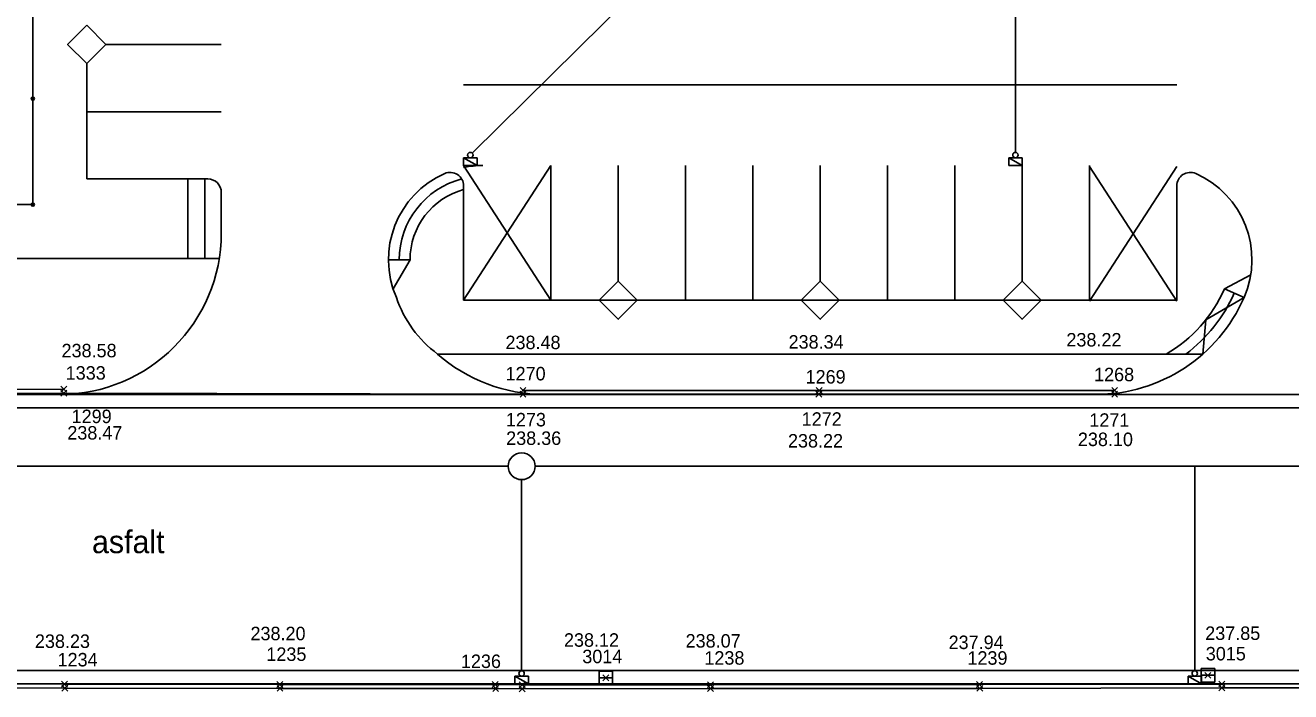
# Model space of a CAD drawing. Extents: x -264205 to -263615, y -1242401 to -1242031.
# Drawn here: x -263972.35 to -263925.35, y -1242312.52 to -1242287.78 of the extents above; entities that cross this region are included whole.
import ezdxf

# ---------------------------------------------------------------- set-up
doc = ezdxf.new("R2010")
doc.units = 0
for name, color, linetype in [('BODY_SYMBOL A CISLO_2-1', 7, 'Continuous'), ('BODY_VYSKA_2-1', 7, 'Continuous'), ('KOORDINACNA_SITUACIA_DSP', 7, 'Continuous'), ('POPIS', 7, 'Continuous'), ('PROJEKT_DRS_TDZ_VODOROVNE', 7, 'Continuous'), ('ROZHRANIE_SO_20-1_a_20-2', 7, 'Continuous'), ('SO_20-1_OBRUBNIKY_DOLNA_HRANA', 7, 'Continuous'), ('SO_20-1_OBRUBNIKY_HORNA_HRANA', 7, 'Continuous'), ('SO_20-1_UV', 7, 'Continuous')]:
    doc.layers.add(name, color=color, linetype=linetype)

msp = doc.modelspace()

# ---------------------------------------------------------------- linework, layer by layer
at = {"layer": 'BODY_SYMBOL A CISLO_2-1'}
for p, q in [((-263971.024, -1242301.4), (-263970.802, -1242301.18)), ((-263970.802, -1242301.4), (-263971.024, -1242301.18)), ((-263971.023, -1242301.549), (-263970.802, -1242301.328)), ((-263970.802, -1242301.549), (-263971.023, -1242301.328)), ((-263953.973, -1242301.441), (-263953.752, -1242301.22)), ((-263953.752, -1242301.441), (-263953.973, -1242301.22)), ((-263953.973, -1242301.588), (-263953.752, -1242301.367)), ((-263953.752, -1242301.588), (-263953.973, -1242301.367)), ((-263942.987, -1242301.586), (-263942.766, -1242301.366)), ((-263942.766, -1242301.586), (-263942.987, -1242301.366)), ((-263942.971, -1242301.448), (-263942.75, -1242301.227)), ((-263942.75, -1242301.448), (-263942.971, -1242301.227)), ((-263931.998, -1242301.441), (-263931.777, -1242301.22)), ((-263931.777, -1242301.441), (-263931.998, -1242301.22)), ((-263931.998, -1242301.585), (-263931.777, -1242301.363)), ((-263931.777, -1242301.585), (-263931.998, -1242301.363)), ((-263971.003, -1242312.353), (-263970.781, -1242312.133)), ((-263970.781, -1242312.353), (-263971.003, -1242312.133)), ((-263963.002, -1242312.359), (-263962.78, -1242312.137)), ((-263962.78, -1242312.359), (-263963.002, -1242312.137)), ((-263955.003, -1242312.366), (-263954.782, -1242312.144)), ((-263954.782, -1242312.366), (-263955.003, -1242312.144)), ((-263954.003, -1242312.377), (-263953.781, -1242312.156)), ((-263953.781, -1242312.377), (-263954.003, -1242312.156)), ((-263950.897, -1242312.115), (-263950.676, -1242311.894)), ((-263950.676, -1242312.115), (-263950.897, -1242311.894)), ((-263947.011, -1242312.372), (-263946.79, -1242312.15)), ((-263946.79, -1242312.372), (-263947.011, -1242312.15)), ((-263937.014, -1242312.363), (-263936.793, -1242312.143)), ((-263936.793, -1242312.363), (-263937.014, -1242312.143)), ((-263928.533, -1242312.022), (-263928.312, -1242311.802)), ((-263928.312, -1242312.022), (-263928.533, -1242311.802)), ((-263928.019, -1242312.346), (-263927.799, -1242312.124)), ((-263927.799, -1242312.346), (-263928.019, -1242312.124)), ((-263928.019, -1242312.346), (-263927.799, -1242312.126)), ((-263927.799, -1242312.346), (-263928.019, -1242312.126)), ((-263970.993, -1242312.498), (-263970.772, -1242312.276)), ((-263970.772, -1242312.498), (-263970.993, -1242312.276)), ((-263962.998, -1242312.507), (-263962.777, -1242312.285)), ((-263962.777, -1242312.507), (-263962.998, -1242312.285)), ((-263954.989, -1242312.514), (-263954.768, -1242312.292)), ((-263954.768, -1242312.514), (-263954.989, -1242312.292)), ((-263954.007, -1242312.521), (-263953.785, -1242312.299)), ((-263953.785, -1242312.521), (-263954.007, -1242312.299)), ((-263947.006, -1242312.516), (-263946.785, -1242312.296)), ((-263946.785, -1242312.516), (-263947.006, -1242312.296)), ((-263937.009, -1242312.507), (-263936.788, -1242312.285)), ((-263936.788, -1242312.507), (-263937.009, -1242312.285)), ((-263928.018, -1242312.492), (-263927.796, -1242312.271)), ((-263927.796, -1242312.492), (-263928.018, -1242312.271)), ((-263928.017, -1242312.492), (-263927.796, -1242312.272)), ((-263927.796, -1242312.492), (-263928.017, -1242312.272))]:
    msp.add_line(p, q, dxfattribs=at)
at = {"layer": 'KOORDINACNA_SITUACIA_DSP'}
for p, q in [((-263972.068, -1242294.432), (-263972.068, -1242255.057)), ((-263955.747, -1242292.522), (-263947.464, -1242284.334)), ((-263935.574, -1242292.492), (-263935.574, -1242284.343)), ((-263970.068, -1242293.482), (-263970.068, -1242289.189)), ((-263972.128, -1242290.495), (-263972.008, -1242290.495)), ((-263972.068, -1242290.555), (-263972.068, -1242290.435)), ((-263956.068, -1242292.692), (-263955.568, -1242292.692)), ((-263956.068, -1242292.982), (-263956.068, -1242292.692)), ((-263956.068, -1242292.692), (-263955.568, -1242292.982)), ((-263956.068, -1242292.692), (-263955.568, -1242292.982)), ((-263955.568, -1242292.692), (-263956.068, -1242292.692)), ((-263955.568, -1242292.692), (-263955.568, -1242292.982)), ((-263955.568, -1242292.982), (-263955.568, -1242292.692)), ((-263935.824, -1242292.692), (-263935.324, -1242292.692)), ((-263935.824, -1242292.982), (-263935.824, -1242292.692)), ((-263935.824, -1242292.692), (-263935.324, -1242292.982)), ((-263935.824, -1242292.692), (-263935.324, -1242292.982)), ((-263935.324, -1242292.692), (-263935.824, -1242292.692)), ((-263935.324, -1242292.692), (-263935.324, -1242292.982)), ((-263935.324, -1242292.982), (-263935.324, -1242292.692)), ((-263955.568, -1242292.982), (-263956.068, -1242292.982)), ((-263935.324, -1242292.982), (-263935.824, -1242292.982)), ((-263970.068, -1242293.482), (-263965.568, -1242293.482)), ((-263966.314, -1242293.482), (-263966.314, -1242296.432)), ((-263965.684, -1242293.482), (-263965.684, -1242296.432)), ((-263956.068, -1242297.982), (-263956.068, -1242293.737)), ((-263929.58, -1242297.982), (-263929.58, -1242293.737)), ((-263972.068, -1242294.492), (-263972.068, -1242294.372)), ((-263965.068, -1242293.982), (-263965.068, -1242295.482)), ((-264045.118, -1242294.432), (-263972.068, -1242294.432)), ((-263972.128, -1242294.432), (-263972.008, -1242294.432)), ((-263927.814, -1242297.562), (-263926.833, -1242297.035)), ((-263927.814, -1242297.562), (-263927.081, -1242297.882)), ((-263929.58, -1242297.982), (-263956.068, -1242297.982)), ((-263928.612, -1242299.982), (-263957.036, -1242299.982)), ((-263971.068, -1242301.482), (-264112.961, -1242301.482)), ((-263932.58, -1242301.482), (-263953.068, -1242301.482)), ((-263954.413, -1242304.147), (-264003.396, -1242304.147)), ((-263904.413, -1242304.147), (-263953.413, -1242304.147)), ((-263928.913, -1242311.742), (-263928.913, -1242304.147)), ((-263953.913, -1242311.742), (-263953.913, -1242304.647)), ((-263954.163, -1242311.942), (-263953.663, -1242311.942)), ((-263954.163, -1242312.232), (-263954.163, -1242311.942)), ((-263954.163, -1242311.942), (-263953.663, -1242312.232)), ((-263954.163, -1242311.942), (-263953.663, -1242312.232)), ((-263953.663, -1242311.942), (-263954.163, -1242311.942)), ((-263953.663, -1242311.942), (-263953.663, -1242312.232)), ((-263953.663, -1242312.232), (-263953.663, -1242311.942)), ((-263929.163, -1242311.942), (-263928.663, -1242311.942)), ((-263929.163, -1242312.232), (-263929.163, -1242311.942)), ((-263929.163, -1242311.942), (-263928.663, -1242312.232)), ((-263929.163, -1242311.942), (-263928.663, -1242312.232)), ((-263928.663, -1242311.942), (-263929.163, -1242311.942)), ((-263928.663, -1242311.942), (-263928.663, -1242312.232)), ((-263928.663, -1242312.232), (-263928.663, -1242311.942)), ((-263980.94, -1242312.232), (-263857.327, -1242312.232)), ((-263953.663, -1242312.232), (-263954.163, -1242312.232)), ((-263928.663, -1242312.232), (-263929.163, -1242312.232))]:
    msp.add_line(p, q, dxfattribs=at)
for points in [[(-263970.068, -1242287.775), (-263969.361, -1242288.482), (-263970.068, -1242289.189), (-263970.775, -1242288.482)], [(-263949.617, -1242297.982), (-263950.324, -1242297.275), (-263951.031, -1242297.982), (-263950.324, -1242298.689)], [(-263942.117, -1242297.982), (-263942.824, -1242297.275), (-263943.531, -1242297.982), (-263942.824, -1242298.689)], [(-263934.617, -1242297.982), (-263935.324, -1242297.275), (-263936.031, -1242297.982), (-263935.324, -1242298.689)]]:
    msp.add_lwpolyline(points, close=True, dxfattribs=at)
for points in [[(-263965.143, -1242296.432), (-264120.018, -1242296.432), (-264120.282, -1242296.432)], [(-263958.859, -1242296.482), (-263958.059, -1242296.482), (-263958.688, -1242297.562)], [(-263927.081, -1242297.882), (-263928.506, -1242298.713), (-263928.612, -1242299.982)]]:
    msp.add_lwpolyline(points, dxfattribs=at)
for centre, radius in [((-263972.068, -1242290.495), 0.06), ((-263955.818, -1242292.592), 0.1), ((-263935.574, -1242292.592), 0.1), ((-263972.068, -1242294.432), 0.06), ((-263953.913, -1242304.147), 0.5), ((-263953.913, -1242311.842), 0.1), ((-263928.913, -1242311.842), 0.1)]:
    msp.add_circle(centre, radius, dxfattribs=at)
for centre, radius, start, end in [((-263955.359, -1242296.482), 3.5, 113.7599, 203.5782), ((-263956.568, -1242293.737), 0.5, 0, 113.7599), ((-263929.08, -1242293.737), 0.5, 66.2401, 180), ((-263930.289, -1242296.482), 3.5, 336.4218, 66.2401), ((-263965.568, -1242293.982), 0.5, 0, 90), ((-263955.359, -1242296.482), 3.1, 104.5457, 180), ((-263955.359, -1242296.482), 2.7, 105.2176, 180), ((-263971.068, -1242295.482), 6, 270, 0), ((-263932.58, -1242295.482), 5.2, 300.0733, 336.4218), ((-263954.444, -1242296.485), 4.353, 198.7173, 233.4513), ((-263932.58, -1242295.482), 6, 270, 336.4218), ((-263932.58, -1242295.482), 5.6, 306.5275, 336.4218), ((-263953.068, -1242295.482), 6, 228.5904, 270)]:
    msp.add_arc(centre, radius, start, end, dxfattribs=at)
at = {"layer": 'PROJEKT_DRS_TDZ_VODOROVNE'}
for p, q in [((-263965.068, -1242288.482), (-263969.361, -1242288.482)), ((-263929.58, -1242289.982), (-263956.068, -1242289.982)), ((-263965.068, -1242290.982), (-263970.068, -1242290.982)), ((-263956.069, -1242297.982), (-263952.825, -1242292.982)), ((-263956.069, -1242292.982), (-263952.825, -1242297.982)), ((-263952.824, -1242297.982), (-263952.824, -1242292.982)), ((-263950.324, -1242297.275), (-263950.324, -1242292.982)), ((-263947.824, -1242297.982), (-263947.824, -1242292.982)), ((-263945.324, -1242297.982), (-263945.324, -1242292.982)), ((-263942.824, -1242297.275), (-263942.824, -1242292.982)), ((-263940.324, -1242297.982), (-263940.324, -1242292.982)), ((-263937.824, -1242297.982), (-263937.824, -1242292.982)), ((-263935.324, -1242297.275), (-263935.324, -1242292.982)), ((-263932.824, -1242297.982), (-263932.824, -1242292.982)), ((-263932.824, -1242298.014), (-263929.58, -1242293.014)), ((-263932.824, -1242293.014), (-263929.58, -1242298.014)), ((-263953.068, -1242301.482), (-263971.068, -1242301.482)), ((-263914.08, -1242301.482), (-263932.58, -1242301.482)), ((-264112.961, -1242301.982), (-263971.806, -1242301.982)), ((-263971.806, -1242301.982), (-263953.068, -1242301.982)), ((-263953.068, -1242301.982), (-263932.58, -1242301.982)), ((-263932.58, -1242301.982), (-263913.841, -1242301.982)), ((-263842.661, -1242311.732), (-263980.94, -1242311.732))]:
    msp.add_line(p, q, dxfattribs=at)
msp.add_arc((-263955.359, -1242296.482), 3.5, 90, 101.6826, dxfattribs=at)
at = {"layer": 'ROZHRANIE_SO_20-1_a_20-2'}
for p, q in [((-263970.912, -1242301.438), (-263953.862, -1242301.477)), ((-263931.888, -1242301.474), (-263913.884, -1242301.489))]:
    msp.add_line(p, q, dxfattribs=at)
at = {"layer": 'SO_20-1_OBRUBNIKY_DOLNA_HRANA'}
for points in [[(-263993.952, -1242301.425), (-263986.921, -1242301.437), (-263979.924, -1242301.441), (-263972.919, -1242301.445), (-263970.912, -1242301.438)], [(-263931.888, -1242301.474), (-263942.877, -1242301.476), (-263953.862, -1242301.477)], [(-264033.805, -1242309.499), (-264025.829, -1242309.934), (-264015.848, -1242310.539), (-264003.863, -1242311.243), (-263994.874, -1242311.606), (-263986.882, -1242311.907), (-263978.856, -1242312.215), (-263970.892, -1242312.243), (-263962.891, -1242312.248), (-263954.893, -1242312.255), (-263953.892, -1242312.266), (-263946.9, -1242312.261), (-263936.904, -1242312.253), (-263927.909, -1242312.236)], [(-263927.909, -1242312.235), (-263920.91, -1242312.234), (-263913.915, -1242312.225), (-263906.912, -1242312.227), (-263898.896, -1242312.208), (-263891.9, -1242312.209), (-263883.905, -1242312.21), (-263878.731, -1242312.212), (-263870.923, -1242312.226), (-263863.907, -1242312.232), (-263855.93, -1242312.232)]]:
    msp.add_lwpolyline(points, dxfattribs=at)
at = {"layer": 'SO_20-1_OBRUBNIKY_HORNA_HRANA'}
for points in [[(-263993.949, -1242301.276), (-263986.923, -1242301.287), (-263979.923, -1242301.293), (-263972.92, -1242301.295), (-263970.913, -1242301.29)], [(-263931.888, -1242301.33), (-263942.861, -1242301.337), (-263953.862, -1242301.33)], [(-264033.819, -1242309.643), (-264025.833, -1242310.082), (-264015.854, -1242310.687), (-264003.872, -1242311.39), (-263994.881, -1242311.753), (-263986.886, -1242312.056), (-263978.896, -1242312.359), (-263970.883, -1242312.387), (-263962.888, -1242312.396), (-263954.878, -1242312.403), (-263953.896, -1242312.41), (-263946.895, -1242312.406), (-263936.899, -1242312.396), (-263927.906, -1242312.382)], [(-263927.907, -1242312.381), (-263920.909, -1242312.378), (-263913.91, -1242312.365), (-263906.907, -1242312.358), (-263898.91, -1242312.357), (-263891.902, -1242312.354), (-263883.907, -1242312.356), (-263878.731, -1242312.358), (-263870.924, -1242312.368), (-263863.913, -1242312.368), (-263855.926, -1242312.378)]]:
    msp.add_lwpolyline(points, dxfattribs=at)
at = {"layer": 'SO_20-1_UV'}
for p, q in [((-263950.786, -1242312.004), (-263950.786, -1242312.004)), ((-263928.422, -1242311.912), (-263928.422, -1242311.912))]:
    msp.add_line(p, q, dxfattribs=at)
for points in [[(-263951.036, -1242312.004), (-263951.036, -1242311.754), (-263950.536, -1242311.754), (-263950.536, -1242312.254), (-263951.036, -1242312.254), (-263951.036, -1242312.004), (-263950.536, -1242312.004)], [(-263928.672, -1242311.912), (-263928.672, -1242311.662), (-263928.172, -1242311.662), (-263928.172, -1242312.162), (-263928.672, -1242312.162), (-263928.672, -1242311.912), (-263928.172, -1242311.912)]]:
    msp.add_lwpolyline(points, dxfattribs=at)

# ---------------------------------------------------------------- texts
at = {"layer": 'BODY_SYMBOL A CISLO_2-1'}
for s, p in [('1333', (-263970.848, -1242300.933)), ('1270', (-263954.51, -1242300.961)), ('1269', (-263943.367, -1242301.077)), ('1268', (-263932.653, -1242300.993)), ('1299', (-263970.627, -1242302.547)), ('1273', (-263954.497, -1242302.669)), ('1272', (-263943.512, -1242302.646)), ('1271', (-263932.829, -1242302.684)), ('1234', (-263971.149, -1242311.582)), ('1235', (-263963.395, -1242311.378)), ('1236', (-263956.168, -1242311.641)), ('3014', (-263951.66, -1242311.462)), ('1238', (-263947.126, -1242311.517)), ('1239', (-263937.356, -1242311.519)), ('3015', (-263928.504, -1242311.36))]:
    msp.add_text(s, height=0.5, dxfattribs=at).set_placement(p)
at = {"layer": 'BODY_VYSKA_2-1'}
for s, p in [('238.48', (-263954.513, -1242299.8)), ('238.34', (-263943.998, -1242299.781)), ('238.22', (-263933.681, -1242299.702)), ('238.58', (-263971.001, -1242300.104)), ('238.47', (-263970.787, -1242303.156)), ('238.36', (-263954.489, -1242303.357)), ('238.22', (-263944.021, -1242303.453)), ('238.10', (-263933.253, -1242303.4)), ('238.20', (-263963.984, -1242310.61)), ('238.12', (-263952.341, -1242310.852)), ('237.85', (-263928.525, -1242310.599)), ('238.23', (-263971.99, -1242310.896)), ('238.07', (-263947.823, -1242310.883)), ('237.94', (-263938.055, -1242310.937))]:
    msp.add_text(s, height=0.5, dxfattribs=at).set_placement(p)
at = {"layer": 'POPIS'}
msp.add_text('asfalt', height=0.8438, dxfattribs=at).set_placement((-263969.87, -1242307.377))

doc.saveas('drawing.dxf')
